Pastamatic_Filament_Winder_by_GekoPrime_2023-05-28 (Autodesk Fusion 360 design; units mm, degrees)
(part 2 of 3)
move "Move3" RotateAngle 90
move "Move4" TranslateX 0 TranslateY 0 TranslateZ -3.5 (= "-bearing_z / 2")
sketch "Sketch13" plane through (0, 0, -44.8284) normal (0, 0, -1) x axis (-1, 0, 0)
  circle C1 centre (0, 0) radius 13
  circle C2 centre (0, 0) radius 13
  circle C3 centre (0, 0) radius 10.1716
  circle C4 centre (0, 0) radius 10.1716
sketch "Sketch14" plane through (0, 0, -56.4284) normal (0, 0, 1) x axis (1, 0, 0)
  line L1 (-9.2583, 1.6082) -> (-8.3641, 1.4537)
  curve K1 (-11.9856, 0.5875) -> (-9.2583, 1.6082)
  curve K2 (-9.2583, -1.6082) -> (-11.9856, -0.5875)
  line L2 (-8.3641, -1.4537) -> (-9.2583, -1.6082)
  line L3 (-8.4354, -4.1409) -> (-7.6212, -3.7403)
  curve K3 (-10.0419, -6.5697) -> (-8.4354, -4.1409)
  curve K4 (-6.5449, -6.7429) -> (-9.3513, -7.5202)
  line L4 (-5.9123, -6.0924) -> (-6.5449, -6.7429)
  line L5 (-4.3904, -8.3082) -> (-3.9672, -7.5055)
  curve K5 (-4.2625, -11.2175) -> (-4.3904, -8.3082)
  curve K6 (-1.3315, -9.3021) -> (-3.145, -11.5805)
  line L6 (-1.2021, -8.404) -> (-1.3315, -9.3021)
  line L7 (1.3315, -9.3021) -> (1.2021, -8.404)
  curve K7 (3.145, -11.5805) -> (1.3315, -9.3021)
  curve K8 (4.3904, -8.3082) -> (4.2625, -11.2175)
  line L8 (3.9672, -7.5055) -> (4.3904, -8.3082)
  line L9 (6.5449, -6.7429) -> (5.9123, -6.0924)
  curve K9 (9.3513, -7.5202) -> (6.5449, -6.7429)
  curve K10 (8.4354, -4.1409) -> (10.0419, -6.5697)
  line L10 (7.6212, -3.7403) -> (8.4354, -4.1409)
  line L11 (9.2583, -1.6082) -> (8.3641, -1.4537)
  curve K11 (11.9856, -0.5875) -> (9.2583, -1.6082)
  curve K12 (9.2583, 1.6082) -> (11.9856, 0.5875)
  line L12 (8.3641, 1.4537) -> (9.2583, 1.6082)
  line L13 (8.4354, 4.1409) -> (7.6212, 3.7403)
  curve K13 (10.0419, 6.5697) -> (8.4354, 4.1409)
  curve K14 (6.5449, 6.7429) -> (9.3513, 7.5202)
  line L14 (5.9123, 6.0924) -> (6.5449, 6.7429)
  line L15 (4.3904, 8.3082) -> (3.9672, 7.5055)
  curve K15 (4.2625, 11.2175) -> (4.3904, 8.3082)
  curve K16 (1.3315, 9.3021) -> (3.145, 11.5805)
  line L16 (1.2021, 8.404) -> (1.3315, 9.3021)
  line L17 (-1.3315, 9.3021) -> (-1.2021, 8.404)
  curve K17 (-3.145, 11.5805) -> (-1.3315, 9.3021)
  curve K18 (-4.3904, 8.3082) -> (-4.2625, 11.2175)
  line L18 (-3.9672, 7.5055) -> (-4.3904, 8.3082)
  line L19 (-6.5449, 6.7429) -> (-5.9123, 6.0924)
  curve K19 (-9.3513, 7.5202) -> (-6.5449, 6.7429)
  curve K20 (-8.4354, 4.1409) -> (-10.0419, 6.5697)
  line L20 (-7.6212, 3.7403) -> (-8.4354, 4.1409)
  arc A1 centre (-8.1939, 2.4391) radius 1 between (-8.3641, 1.4537) and (-7.2354, 2.1538)
  arc A2 centre (0, 0) radius 12 clockwise from (-11.9856, -0.5875) to (-11.9856, 0.5875)
  arc A3 centre (-8.1939, -2.4391) radius 1 between (-7.2354, -2.1538) and (-8.3641, -1.4537)
  arc A4 centre (0, 0) radius 7.5492 clockwise from (-7.1196, -2.5104) to (-7.2354, -2.1538)
  arc A5 centre (-8.0626, -2.843) radius 1 between (-7.6212, -3.7403) and (-7.1196, -2.5104)
  arc A6 centre (0, 0) radius 12 clockwise from (-9.3513, -7.5202) to (-10.0419, -6.5697)
  arc A7 centre (-5.1953, -6.7895) radius 1 between (-4.5876, -5.9953) and (-5.9123, -6.0924)
  arc A8 centre (0, 0) radius 7.5492 clockwise from (-4.2842, -6.2158) to (-4.5876, -5.9953)
  arc A9 centre (-4.8518, -7.0391) radius 1 between (-3.9672, -7.5055) and (-4.2842, -6.2158)
  arc A10 centre (0, 0) radius 12 clockwise from (-3.145, -11.5805) to (-4.2625, -11.2175)
  arc A11 centre (-0.2123, -8.5466) radius 1 between (-0.1875, -7.5469) and (-1.2021, -8.404)
  arc A12 centre (0, 0) radius 7.5492 clockwise from (0.1875, -7.5469) to (-0.1875, -7.5469)
  arc A13 centre (0.2123, -8.5466) radius 1 between (1.2021, -8.404) and (0.1875, -7.5469)
  arc A14 centre (0, 0) radius 12 clockwise from (4.2625, -11.2175) to (3.145, -11.5805)
  arc A15 centre (4.8518, -7.0391) radius 1 between (4.2842, -6.2158) and (3.9672, -7.5055)
  arc A16 centre (0, 0) radius 7.5492 clockwise from (4.5876, -5.9953) to (4.2842, -6.2158)
  arc A17 centre (5.1953, -6.7895) radius 1 between (5.9123, -6.0924) and (4.5876, -5.9953)
  arc A18 centre (0, 0) radius 12 clockwise from (10.0419, -6.5697) to (9.3513, -7.5202)
  arc A19 centre (8.0626, -2.843) radius 1 between (7.1196, -2.5104) and (7.6212, -3.7403)
  arc A20 centre (0, 0) radius 7.5492 clockwise from (7.2354, -2.1538) to (7.1196, -2.5104)
  arc A21 centre (8.1939, -2.4391) radius 1 between (8.3641, -1.4537) and (7.2354, -2.1538)
  arc A22 centre (0, 0) radius 12 clockwise from (11.9856, 0.5875) to (11.9856, -0.5875)
  arc A23 centre (8.1939, 2.4391) radius 1 between (7.2354, 2.1538) and (8.3641, 1.4537)
  arc A24 centre (0, 0) radius 7.5492 clockwise from (7.1196, 2.5104) to (7.2354, 2.1538)
  arc A25 centre (8.0626, 2.843) radius 1 between (7.6212, 3.7403) and (7.1196, 2.5104)
  arc A26 centre (0, 0) radius 12 clockwise from (9.3513, 7.5202) to (10.0419, 6.5697)
  arc A27 centre (5.1953, 6.7895) radius 1 between (4.5876, 5.9953) and (5.9123, 6.0924)
  arc A28 centre (0, 0) radius 7.5492 clockwise from (4.2842, 6.2158) to (4.5876, 5.9953)
  arc A29 centre (4.8518, 7.0391) radius 1 between (3.9672, 7.5055) and (4.2842, 6.2158)
  arc A30 centre (0, 0) radius 12 clockwise from (3.145, 11.5805) to (4.2625, 11.2175)
  arc A31 centre (0.2123, 8.5466) radius 1 between (0.1875, 7.5469) and (1.2021, 8.404)
  arc A32 centre (0, 0) radius 7.5492 clockwise from (-0.1875, 7.5469) to (0.1875, 7.5469)
  arc A33 centre (-0.2123, 8.5466) radius 1 between (-1.2021, 8.404) and (-0.1875, 7.5469)
  arc A34 centre (0, 0) radius 12 clockwise from (-4.2625, 11.2175) to (-3.145, 11.5805)
  arc A35 centre (-4.8518, 7.0391) radius 1 between (-4.2842, 6.2158) and (-3.9672, 7.5055)
  arc A36 centre (0, 0) radius 7.5492 clockwise from (-4.5876, 5.9953) to (-4.2842, 6.2158)
  arc A37 centre (-5.1953, 6.7895) radius 1 between (-5.9123, 6.0924) and (-4.5876, 5.9953)
  arc A38 centre (0, 0) radius 12 clockwise from (-10.0419, 6.5697) to (-9.3513, 7.5202)
  arc A39 centre (-8.0626, 2.843) radius 1 between (-7.1196, 2.5104) and (-7.6212, 3.7403)
  arc A40 centre (0, 0) radius 7.5492 clockwise from (-7.2354, 2.1538) to (-7.1196, 2.5104)
loft "Loft7" sketch "Sketch13" + "Sketch14"
sketch "Sketch15" plane through (0, 0, -75.0284) normal (0, 0, 1) x axis (1, 0, 0)
  circle C1 centre (0, 0) radius 13
  circle C2 centre (0, 0) radius 13
sketch "Sketch16" plane through (0, 0, -63.4284) normal (0, 0, -1) x axis (-1, 0, 0)
  line L1 (8.4354, 4.1409) -> (7.6212, 3.7403)
  curve K1 (10.0419, 6.5697) -> (8.4354, 4.1409)
  curve K2 (6.5449, 6.7429) -> (9.3513, 7.5202)
  line L2 (5.9123, 6.0924) -> (6.5449, 6.7429)
  line L3 (4.3904, 8.3082) -> (3.9672, 7.5055)
  curve K3 (4.2625, 11.2175) -> (4.3904, 8.3082)
  curve K4 (1.3315, 9.3021) -> (3.145, 11.5805)
  line L4 (1.2021, 8.404) -> (1.3315, 9.3021)
  line L5 (-1.3315, 9.3021) -> (-1.2021, 8.404)
  curve K5 (-3.145, 11.5805) -> (-1.3315, 9.3021)
  curve K6 (-4.3904, 8.3082) -> (-4.2625, 11.2175)
  line L6 (-3.9672, 7.5055) -> (-4.3904, 8.3082)
  line L7 (-6.5449, 6.7429) -> (-5.9123, 6.0924)
  curve K7 (-9.3513, 7.5202) -> (-6.5449, 6.7429)
  curve K8 (-8.4354, 4.1409) -> (-10.0419, 6.5697)
  line L8 (-7.6212, 3.7403) -> (-8.4354, 4.1409)
  line L9 (-9.2583, 1.6082) -> (-8.3641, 1.4537)
  curve K9 (-11.9856, 0.5875) -> (-9.2583, 1.6082)
  curve K10 (-9.2583, -1.6082) -> (-11.9856, -0.5875)
  line L10 (-8.3641, -1.4537) -> (-9.2583, -1.6082)
  line L11 (-8.4354, -4.1409) -> (-7.6212, -3.7403)
  curve K11 (-10.0419, -6.5697) -> (-8.4354, -4.1409)
  curve K12 (-6.5449, -6.7429) -> (-9.3513, -7.5202)
  line L12 (-5.9123, -6.0924) -> (-6.5449, -6.7429)
  line L13 (-4.3904, -8.3082) -> (-3.9672, -7.5055)
  curve K13 (-4.2625, -11.2175) -> (-4.3904, -8.3082)
  curve K14 (-1.3315, -9.3021) -> (-3.145, -11.5805)
  line L14 (-1.2021, -8.404) -> (-1.3315, -9.3021)
  line L15 (1.3315, -9.3021) -> (1.2021, -8.404)
  curve K15 (3.145, -11.5805) -> (1.3315, -9.3021)
  curve K16 (4.3904, -8.3082) -> (4.2625, -11.2175)
  line L16 (3.9672, -7.5055) -> (4.3904, -8.3082)
  line L17 (6.5449, -6.7429) -> (5.9123, -6.0924)
  curve K17 (9.3513, -7.5202) -> (6.5449, -6.7429)
  curve K18 (8.4354, -4.1409) -> (10.0419, -6.5697)
  line L18 (7.6212, -3.7403) -> (8.4354, -4.1409)
  line L19 (9.2583, -1.6082) -> (8.3641, -1.4537)
  curve K19 (11.9856, -0.5875) -> (9.2583, -1.6082)
  curve K20 (9.2583, 1.6082) -> (11.9856, 0.5875)
  line L20 (8.3641, 1.4537) -> (9.2583, 1.6082)
  line L21 (8.4354, 4.1409) -> (7.6212, 3.7403)
  curve K21 (10.0419, 6.5697) -> (8.4354, 4.1409)
  curve K22 (6.5449, 6.7429) -> (9.3513, 7.5202)
  line L22 (5.9123, 6.0924) -> (6.5449, 6.7429)
  line L23 (4.3904, 8.3082) -> (3.9672, 7.5055)
  curve K23 (4.2625, 11.2175) -> (4.3904, 8.3082)
  curve K24 (1.3315, 9.3021) -> (3.145, 11.5805)
  line L24 (1.2021, 8.404) -> (1.3315, 9.3021)
  line L25 (-1.3315, 9.3021) -> (-1.2021, 8.404)
  curve K25 (-3.145, 11.5805) -> (-1.3315, 9.3021)
  curve K26 (-4.3904, 8.3082) -> (-4.2625, 11.2175)
  line L26 (-3.9672, 7.5055) -> (-4.3904, 8.3082)
  line L27 (-6.5449, 6.7429) -> (-5.9123, 6.0924)
  curve K27 (-9.3513, 7.5202) -> (-6.5449, 6.7429)
  curve K28 (-8.4354, 4.1409) -> (-10.0419, 6.5697)
  line L28 (-7.6212, 3.7403) -> (-8.4354, 4.1409)
  line L29 (-9.2583, 1.6082) -> (-8.3641, 1.4537)
  curve K29 (-11.9856, 0.5875) -> (-9.2583, 1.6082)
  curve K30 (-9.2583, -1.6082) -> (-11.9856, -0.5875)
  line L30 (-8.3641, -1.4537) -> (-9.2583, -1.6082)
  line L31 (-8.4354, -4.1409) -> (-7.6212, -3.7403)
  curve K31 (-10.0419, -6.5697) -> (-8.4354, -4.1409)
  curve K32 (-6.5449, -6.7429) -> (-9.3513, -7.5202)
  line L32 (-5.9123, -6.0924) -> (-6.5449, -6.7429)
  line L33 (-4.3904, -8.3082) -> (-3.9672, -7.5055)
  curve K33 (-4.2625, -11.2175) -> (-4.3904, -8.3082)
  curve K34 (-1.3315, -9.3021) -> (-3.145, -11.5805)
  line L34 (-1.2021, -8.404) -> (-1.3315, -9.3021)
  line L35 (1.3315, -9.3021) -> (1.2021, -8.404)
  curve K35 (3.145, -11.5805) -> (1.3315, -9.3021)
  curve K36 (4.3904, -8.3082) -> (4.2625, -11.2175)
  line L36 (3.9672, -7.5055) -> (4.3904, -8.3082)
  line L37 (6.5449, -6.7429) -> (5.9123, -6.0924)
  curve K37 (9.3513, -7.5202) -> (6.5449, -6.7429)
  curve K38 (8.4354, -4.1409) -> (10.0419, -6.5697)
  line L38 (7.6212, -3.7403) -> (8.4354, -4.1409)
  line L39 (9.2583, -1.6082) -> (8.3641, -1.4537)
  curve K39 (11.9856, -0.5875) -> (9.2583, -1.6082)
  curve K40 (9.2583, 1.6082) -> (11.9856, 0.5875)
  line L40 (8.3641, 1.4537) -> (9.2583, 1.6082)
  arc A1 centre (8.1939, 2.4391) radius 1 between (7.2354, 2.1538) and (8.3641, 1.4537)
  arc A2 centre (0, 0) radius 7.5492 clockwise from (7.1196, 2.5104) to (7.2354, 2.1538)
  arc A3 centre (8.0626, 2.843) radius 1 between (7.6212, 3.7403) and (7.1196, 2.5104)
  arc A4 centre (0, 0) radius 12 clockwise from (9.3513, 7.5202) to (10.0419, 6.5697)
  arc A5 centre (5.1953, 6.7895) radius 1 between (4.5876, 5.9953) and (5.9123, 6.0924)
  arc A6 centre (0, 0) radius 7.5492 clockwise from (4.2842, 6.2158) to (4.5876, 5.9953)
  arc A7 centre (4.8518, 7.0391) radius 1 between (3.9672, 7.5055) and (4.2842, 6.2158)
  arc A8 centre (0, 0) radius 12 clockwise from (3.145, 11.5805) to (4.2625, 11.2175)
  arc A9 centre (0.2123, 8.5466) radius 1 between (0.1875, 7.5469) and (1.2021, 8.404)
  arc A10 centre (0, 0) radius 7.5492 clockwise from (-0.1875, 7.5469) to (0.1875, 7.5469)
  arc A11 centre (-0.2123, 8.5466) radius 1 between (-1.2021, 8.404) and (-0.1875, 7.5469)
  arc A12 centre (0, 0) radius 12 clockwise from (-4.2625, 11.2175) to (-3.145, 11.5805)
  arc A13 centre (-4.8518, 7.0391) radius 1 between (-4.2842, 6.2158) and (-3.9672, 7.5055)
  arc A14 centre (0, 0) radius 7.5492 clockwise from (-4.5876, 5.9953) to (-4.2842, 6.2158)
  arc A15 centre (-5.1953, 6.7895) radius 1 between (-5.9123, 6.0924) and (-4.5876, 5.9953)
  arc A16 centre (0, 0) radius 12 clockwise from (-10.0419, 6.5697) to (-9.3513, 7.5202)
  arc A17 centre (-8.0626, 2.843) radius 1 between (-7.1196, 2.5104) and (-7.6212, 3.7403)
  arc A18 centre (0, 0) radius 7.5492 clockwise from (-7.2354, 2.1538) to (-7.1196, 2.5104)
  arc A19 centre (-8.1939, 2.4391) radius 1 between (-8.3641, 1.4537) and (-7.2354, 2.1538)
  arc A20 centre (0, 0) radius 12 clockwise from (-11.9856, -0.5875) to (-11.9856, 0.5875)
  arc A21 centre (-8.1939, -2.4391) radius 1 between (-7.2354, -2.1538) and (-8.3641, -1.4537)
  arc A22 centre (0, 0) radius 7.5492 clockwise from (-7.1196, -2.5104) to (-7.2354, -2.1538)
  arc A23 centre (-8.0626, -2.843) radius 1 between (-7.6212, -3.7403) and (-7.1196, -2.5104)
  arc A24 centre (0, 0) radius 12 clockwise from (-9.3513, -7.5202) to (-10.0419, -6.5697)
  arc A25 centre (-5.1953, -6.7895) radius 1 between (-4.5876, -5.9953) and (-5.9123, -6.0924)
  arc A26 centre (0, 0) radius 7.5492 clockwise from (-4.2842, -6.2158) to (-4.5876, -5.9953)
  arc A27 centre (-4.8518, -7.0391) radius 1 between (-3.9672, -7.5055) and (-4.2842, -6.2158)
  arc A28 centre (0, 0) radius 12 clockwise from (-3.145, -11.5805) to (-4.2625, -11.2175)
  arc A29 centre (-0.2123, -8.5466) radius 1 between (-0.1875, -7.5469) and (-1.2021, -8.404)
  arc A30 centre (0, 0) radius 7.5492 clockwise from (0.1875, -7.5469) to (-0.1875, -7.5469)
  arc A31 centre (0.2123, -8.5466) radius 1 between (1.2021, -8.404) and (0.1875, -7.5469)
  arc A32 centre (0, 0) radius 12 clockwise from (4.2625, -11.2175) to (3.145, -11.5805)
  arc A33 centre (4.8518, -7.0391) radius 1 between (4.2842, -6.2158) and (3.9672, -7.5055)
  arc A34 centre (0, 0) radius 7.5492 clockwise from (4.5876, -5.9953) to (4.2842, -6.2158)
  arc A35 centre (5.1953, -6.7895) radius 1 between (5.9123, -6.0924) and (4.5876, -5.9953)
  arc A36 centre (0, 0) radius 12 clockwise from (10.0419, -6.5697) to (9.3513, -7.5202)
  arc A37 centre (8.0626, -2.843) radius 1 between (7.1196, -2.5104) and (7.6212, -3.7403)
  arc A38 centre (0, 0) radius 7.5492 clockwise from (7.2354, -2.1538) to (7.1196, -2.5104)
  arc A39 centre (8.1939, -2.4391) radius 1 between (8.3641, -1.4537) and (7.2354, -2.1538)
  arc A40 centre (0, 0) radius 12 clockwise from (11.9856, 0.5875) to (11.9856, -0.5875)
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loft "Loft10" sketch "Sketch15" + "Sketch16"
combine "Combine24" bodies "spur_gear_10t_7mm"
sketch "drive" plane through (0, 0, 0) normal (0, 0, 1) x axis (-1, 0, 0)
  line L1 (-1.963, -3.4) -> (1.963, -3.4)
  line L2 (0, 0) -> (1.963, -3.4)
  line L3 (-1.963, -3.4) -> (0, 0)
  line L4 (-1.963, -5.4) -> (1.963, -5.4)
  line L5 (2.963, -5.1321) -> (1.963, -3.4)
  line L6 (-2.963, -5.1321) -> (-1.963, -3.4)
  circle C1 centre (0, 0) radius 15
  circle C2 centre (0, 0) radius 3.4
  arc A1 centre (1.963, -3.4) radius 2 clockwise from (2.963, -5.1321) to (1.963, -5.4)
  arc A2 centre (-1.963, -3.4) radius 2 clockwise from (-1.963, -5.4) to (-2.963, -5.1321)
  arc A3 centre (0, -3.4) radius 0.4156 clockwise from (0.4156, -3.4) to (-0.3636, -3.1986)
  arc A4 centre (0, -3.4) radius 2.4156 clockwise from (1.3547, -5.4) to (-1.3547, -5.4)
  point P1 (0, 0)
  point P3 (0, 0)
  point P6 (0, 0)
  point P4 (1.963, -3.4)
  point P7 (1.963, -3.4)
  point P5 (-1.963, -3.4)
  point P10 (-1.963, -3.4)
  point P13 (1.963, -3.4)
  point P16 (0.4156, -3.4)
  point P14 (0, -3.4)
  point P19 (1.3547, -5.4)
  point P17 (0, -3.4)
  point P18 (-1.3547, -5.4)
  coincident P1 P3
  tangent C2 L1
  coincident P3 P6
  equal L2 L3
  coincident P4 P7
  coincident P5 P10
  coincident P7 P13
  collinear L2 L5
  collinear L3 L6
  tangent A2 L4
  tangent A1 L4
  parallel L1 L4
  coincident L1 P16
  midpoint L1 P14
  coincident L4 P19
  coincident P14 P17
  coincident L4 P18
  horizontal L1
  dimension "d888" diameter C2 = 6.8 (= "drive_span + clearance_loose / 2")
  dimension "d889" angle L2 L3 = 60 (= "( 360 / drive_n_sides ) * 1 deg")
  dimension "d890" distance L1 L4 = 2 (= "wall_thickness")
  dimension "d892" distance A3 A4 = 2 (= "wall_thickness")
  dimension "d893" radius A3 = 0.4156 (= "drive_span / 16")
extrude "Extrude18" sketch "drive" profile of L1 L2 L3 no distance stored
circular_pattern "C-Pattern7" TotalAngle 360
loft "Loft14"
extrude "Extrude19" add of existing geometry blind 2 (= "wall_thickness") taper -45
sketch "Sketch1" plane through (0, 0, 0) normal (0, 0, 1) x axis (1, 0, 0)
  line L1 (0, 0) -> (0, 16.5831)
  line L2 (0, 125) -> (0, -125)
  line L3 (25, 16.5831) -> (-25, 16.5831)
  line L4 (0, 0) -> (-25, 16.5831)
  line L5 (25, 16.5831) -> (0, 0)
  line L6 (62.3842, 108.049) -> (175.0785, 108.049)
  line L7 (183.0785, 128.049) -> (-95, 128.049)
  line L8 (112.9635, 75.7732) -> (62.3842, 108.049)
  line L9 (112.9635, 75.7732) -> (175.0785, 108.049)
  line L10 (-18.3848, 118.5932) -> (13.1117, 87.0967)
  line L11 (183.0785, 128.049) -> (183.0785, 108.049)
  line L12 (1.8396, 51.0572) -> (30.6569, 22.24)
  line L13 (0.277, 151.3971) -> (-7.0711, 144.049)
  line L14 (183.0785, 144.049) -> (-95, 144.049)
  line L15 (183.0785, 128.049) -> (183.0785, 144.049)
  line L16 (0, 144.049) -> (0, 125)
  line L17 (-24.4187, 144.049) -> (-24.4187, 128.049)
  line L18 (-7.0711, 129.9069) -> (-7.0711, 144.049)
  line L19 (-206.2464, 96.6381) -> (-220.8848, 96.6381)
  line L20 (-220.1543, 105.5872) -> (-211.2052, 96.6381)
  line L21 (112.9635, 75.7732) -> (94.777, 86.2732)
  line L22 (131.15, 86.2732) -> (112.9635, 75.7732)
  line L23 (94.777, 86.2732) -> (131.15, 86.2732)
  line L24 (175, 65.7732) -> (67, 65.7732)
  line L25 (128.2235, 66.3204) -> (179.5938, 101.4452)
  line L26 (57.0973, 102.045) -> (97.4011, 66.5555)
  line L27 (151.8964, 82.5069) -> (143.5323, 94.7396)
  line L28 (74.8858, 86.3813) -> (83.5193, 96.1861)
  line L29 (128.2235, 66.3204) -> (119.6113, 76.6889)
  line L30 (97.4011, 66.5555) -> (106.0346, 76.3603)
  line L31 (4.1421, 126.978) -> (7.0711, 129.9069)
  line L32 (-4.1421, 126.978) -> (4.1421, 126.978)
  line L33 (-7.0711, 129.9069) -> (-4.1421, 126.978)
  line L34 (7.0711, 129.9069) -> (7.0711, 144.049)
  line L35 (-7.0711, 129.9069) -> (7.0711, 129.9069)
  line L36 (40, -14) -> (-52.1436, -14)
  line L37 (-21.6788, -11.5706) -> (-32.3575, 13.4419)
  line L38 (32.3575, 13.4419) -> (21.6788, -11.5706)
  line L39 (-14, 0) -> (-14, -10)
  line L40 (14, -10) -> (14, 0)
  line L41 (167.0785, 128.049) -> (167.0785, 108.049)
  line L42 (-180.3192, 97.2293) -> (-165.6808, 97.2293)
  line L43 (18.7877, 34.1091) -> (6.8934, 22.2148)
  line L44 (-24.002, 39.3233) -> (-6.8934, 22.2148)
  line L45 (24.4187, 144.049) -> (24.4187, 128.049)
  line L46 (-24.4187, 124.978) -> (-24.4187, 128.049)
  line L47 (24.4187, 124.978) -> (-24.4187, 124.978)
  line L48 (24.4187, 128.049) -> (24.4187, 124.978)
  circle C1 centre (0, 0) radius 125
  circle C2 centre (-25, 16.5831) radius 20
  circle C3 centre (25, 16.5831) radius 20
  circle C4 centre (62.3842, 108.049) radius 10
  circle C5 centre (112.9635, 75.7732) radius 50
  circle C6 centre (0, 0) radius 10
  circle C7 centre (112.9635, 75.7732) radius 10
  circle C8 centre (175.0785, 108.049) radius 20
  circle C9 centre (19.6153, 82.1488) radius 20
  circle C10 centre (-7.04, 52.3244) radius 20
  arc A1 centre (118.7313, -33.2588) radius 152.1279 clockwise from (-25, 16.5831) to (175.0785, 108.049)
  circle C11 centre (25, 16.5831) radius 8
  circle C12 centre (-25, 16.5831) radius 8
  circle C13 centre (-7.04, 52.3244) radius 8
  circle C14 centre (19.6153, 82.1488) radius 8
  circle C15 centre (175.0785, 108.049) radius 8
  arc A2 centre (118.7313, -33.2588) radius 144.1279 clockwise from (-17.4416, 13.9621) to (172.1153, 100.618)
  arc A3 centre (118.7313, -33.2588) radius 160.1279 clockwise from (-32.5585, 19.2039) to (178.0416, 115.48)
  arc A4 centre (0, 136.978) radius 10 clockwise from (7.0711, 144.049) to (-7.0711, 144.049)
  arc A5 centre (175.0785, 108.049) radius 8 clockwise from (178.0416, 115.48) to (172.1153, 100.618)
  arc A6 centre (-25, 16.5831) radius 8 clockwise from (-17.4416, 13.9621) to (-32.5585, 19.2039)
  circle C16 centre (-25, 16.5831) radius 24
  circle C17 centre (-7.04, 52.3244) radius 24
  circle C18 centre (19.6153, 82.1488) radius 24
  circle C19 centre (62.3842, 108.049) radius 14
  circle C20 centre (175.0785, 108.049) radius 24
  circle C21 centre (25, 16.5831) radius 24
  circle C22 centre (-25, 16.5831) radius 4.15
  circle C23 centre (25, 16.5831) radius 4.15
  circle C24 centre (-7.04, 52.3244) radius 4.15
  circle C25 centre (19.6153, 82.1488) radius 4.15
  circle C26 centre (62.3842, 108.049) radius 4.15
  circle C27 centre (175.0785, 108.049) radius 4.15
  circle C28 centre (-213.5656, 93.4087) radius 4
  circle C29 centre (-213.5656, 93.4087) radius 8
  circle C30 centre (131.15, 86.2732) radius 4.15
  circle C31 centre (94.777, 86.2732) radius 4.15
  circle C32 centre (131.15, 86.2732) radius 11
  circle C33 centre (94.777, 86.2732) radius 11
  arc A7 centre (112.9635, 75.7732) radius 12 clockwise from (102.2684, 70.3312) to (123.6586, 70.3312)
  arc A8 centre (126.4535, 68.9091) radius 3.1359 clockwise from (128.2235, 66.3204) to (123.6586, 70.3312)
  arc A9 centre (99.4735, 68.9091) radius 3.1359 clockwise from (102.2684, 70.3312) to (97.4011, 66.5555)
  circle C34 centre (131.15, 86.2732) radius 15
  circle C35 centre (94.777, 86.2732) radius 15
  circle C36 centre (0, 0) radius 100
  circle C37 centre (112.9635, 75.7732) radius 54
  circle C38 centre (0, 16.5831) radius 1
  circle C39 centre (0, 0) radius 14
  circle C40 centre (62.3842, 108.049) radius 30
  circle C41 centre (62.3842, 108.049) radius 34
  arc A10 centre (-18, -10) radius 4 clockwise from (-14, -10) to (-21.6788, -11.5706)
  arc A11 centre (18, -10) radius 4 clockwise from (21.6788, -11.5706) to (14, -10)
  arc A12 centre (0, 136.978) radius 26 clockwise from (24.4187, 128.049) to (-24.4187, 128.049)
  circle C42 centre (62.3842, 108.049) radius 8
  circle C43 centre (-173, 94) radius 4
  circle C44 centre (-173, 94) radius 8
  circle C45 centre (17.5, 11.6082) radius 4.15
  circle C46 centre (17.5, 11.6082) radius 11
  circle C47 centre (17.5, 11.6082) radius 15
  circle C48 centre (-17.5, 11.6082) radius 4.15
  circle C49 centre (-17.5, 11.6082) radius 11
  circle C50 centre (-17.5, 11.6082) radius 15
  circle C51 centre (62.3842, 108.049) radius 36
  point P1 (0, 0)
  point P2 (0, 0)
  point P9 (0, 0)
  point P10 (0, -125)
  point P11 (0, 125)
  point P7 (0, 0)
  point P15 (-7.04, 52.3244)
  point P4 (25, 16.5831)
  point P20 (25, 16.5831)
  point P8 (0, 16.5831)
  point P18 (-25, 16.5831)
  point P19 (-25, 16.5831)
  point P3 (-25, 16.5831)
  point P21 (-25, 16.5831)
  point P14 (19.6153, 82.1488)
  point P22 (-25, 16.5831)
  point P23 (0, 0)
  point P24 (0, 0)
  point P25 (25, 16.5831)
  point P13 (175.0785, 108.049)
  point P26 (175.0785, 108.049)
  point P5 (62.3842, 108.049)
  point P27 (62.3842, 108.049)
  point P30 (62.3842, 108.049)
  point P6 (112.9635, 75.7732)
  point P31 (112.9635, 75.7732)
  point P32 (175.0785, 108.049)
  point P12 (112.9635, 75.7732)
  point P33 (112.9635, 75.7732)
  point P34 (25, 16.5831)
  point P38 (175.0785, 108.049)
  point P41 (-17.4416, 13.9621)
  point P17 (175.0785, 108.049)
  point P40 (172.1153, 100.618)
  point P42 (-32.5585, 19.2039)
  point P45 (-32.5585, 19.2039)
  point P39 (118.7313, -33.2588)
  point P43 (118.7313, -33.2588)
  point P16 (118.7313, -33.2588)
  point P47 (-24.4187, 128.049)
  point P48 (183.0785, 108.049)
  point P49 (183.0785, 128.049)
  point P53 (175.0785, 108.049)
  point P56 (-32.5585, 19.2039)
  point P35 (-25, 16.5831)
  point P55 (-25, 16.5831)
  point P69 (30.6569, 22.24)
  point P70 (1.8396, 51.0572)
  point P44 (178.0416, 115.48)
  point P54 (178.0416, 115.48)
  point P72 (-32.3575, 13.4419)
  point P73 (32.3575, 13.4419)
  point P29 (183.0785, 128.049)
  point P52 (7.0711, 144.049)
  point P76 (-7.0711, 144.049)
  point P51 (-7.0711, 144.049)
  point P77 (0, 144.049)
  point P50 (0, 136.978)
  point P78 (-24.4187, 144.049)
  point P79 (0, 25.5242)
  point P80 (-7.0711, 129.9069)
  point P83 (-220.8848, 96.6381)
  point P86 (-206.2464, 96.6381)
  point P84 (-211.2052, 96.6381)
  point P88 (94.777, 86.2732)
  point P91 (94.777, 86.2732)
  point P92 (112.9635, 75.7732)
  point P93 (112.9635, 75.7732)
  point P89 (131.15, 86.2732)
  point P94 (131.15, 86.2732)
  point P96 (112.9635, 75.7732)
  point P105 (179.5938, 101.4452)
  point P109 (143.5323, 94.7396)
  point P110 (151.8964, 82.5069)
  point P111 (83.5193, 96.1861)
  point P112 (74.8858, 86.3813)
  point P113 (119.6113, 76.6889)
  point P114 (106.0346, 76.3603)
  point P115 (7.0711, 129.9069)
  point P118 (0, 0)
  point P95 (94.777, 86.2732)
  point P90 (94.777, 86.2732)
  point P120 (0, 16.5831)
  point P132 (-14, 0)
  point P133 (14, 0)
  point P134 (167.0785, 108.049)
  point P135 (167.0785, 128.049)
  point P137 (-24.4187, 128.049)
  point P136 (0, 136.978)
  point P138 (24.4187, 128.049)
  point P46 (13.1117, 87.0967)
  point P139 (-18.3848, 118.5932)
  point P106 (57.0973, 102.045)
  point P67 (62.3842, 108.049)
  point P123 (62.3842, 108.049)
  point P60 (62.3842, 108.049)
  point P122 (62.3842, 108.049)
  point P143 (-165.6808, 97.2293)
  point P144 (-180.3192, 97.2293)
  point P147 (17.5, 11.6082)
  point P148 (-17.5, 11.6082)
  point P152 (6.8934, 22.2148)
  point P153 (18.7877, 34.1091)
  point P154 (-6.8934, 22.2148)
  point P155 (-24.002, 39.3233)
  point P156 (24.4187, 144.049)
  point P157 (0, 100)
  point P119 (112.9635, 75.7732)
  coincident P1 P2
  concentric C1 C6
  tangent C2 C6
  coincident P1 P9
  vertical L1
  coincident C1 P10
  coincident C1 P11
  vertical L2
  midpoint P7 L2
  concentric C5 C7
  tangent C9 C10
  tangent C2 C10
  tangent C3 C6
  coincident P15 A1
  coincident P4 P20
  midpoint P8 L3
  coincident P18 P19
  horizontal L3
  tangent C5 C8
  coincident P3 P21
  coincident P14 A1
  coincident P3 P19
  coincident P21 P22
  coincident P1 P23
  coincident P2 P24
  coincident P4 P25
  coincident P13 P26
  coincident P5 P27
  coincident P5 A1
  horizontal L6
  horizontal L7
  equal C2 C10
  equal C2 C9
  equal C2 C8
  coincident P5 P30
  coincident P6 P31
  coincident P13 P32
  coincident P12 P33
  coincident P20 P34
  concentric C2 C12
  concentric C10 C13
  concentric C9 C14
  coincident P26 P38
  equal C11 C12
  equal C12 C13
  equal C12 C15
  tangent C12 A2
  coincident C12 P41
  coincident P17 P38
  coincident C15 P40
  coincident P42 P45
  coincident P39 P43
  coincident C12 P42
  coincident P16 P43
  tangent C12 A3
  coincident L7 P47
  coincident C15 P48
  coincident L7 P49
  perpendicular L7 L11
  tangent C15 L11
  coincident P13 P53
  coincident P42 P56
  coincident P35 P55
  concentric A6 C16
  concentric C13 C17
  concentric C14 C18
  concentric C15 C20
  equal C16 C17
  equal C16 C18
  equal C16 C20
  concentric C3 C21
  equal C16 C21
  concentric C16 C22
  concentric C3 C23
  concentric C13 C24
  concentric C14 C25
  concentric C4 C26
  concentric A5 C27
  equal C22 C23
  equal C22 C24
  equal C22 C25
  equal C22 C27
  coincident C11 P69
  coincident A2 P70
  tangent C11 L12
  tangent A4 L13
  coincident P44 P54
  tangent A2 A5
  coincident C12 P72
  coincident C11 P73
  perpendicular L11 L14
  perpendicular L14 L15
  coincident P29 P49
  coincident P52 L14
  coincident L14 P76
  coincident P51 P76
  coincident L14 P77
  perpendicular L14 L16
  coincident P50 L16
  coincident L14 P78
  perpendicular L14 L17
  coincident L2 P79
  coincident A4 P80
  concentric C28 C29
  horizontal L19
  coincident C29 P83
  coincident C29 P86
  coincident P84 L19
  coincident C28 P84
  concentric C30 C32
  equal C22 C31
  equal C22 C30
  equal C32 C33
  tangent C7 C32
  tangent C7 C33
  coincident P88 P91
  coincident P6 P92
  coincident P12 P93
  coincident P89 P94
  horizontal L23
  coincident P6 P96
  tangent A7 A8
  horizontal L24
  tangent C7 L24
  tangent A8 L24
  tangent A9 L24
  tangent A7 A9
  coincident A5 P105
  tangent A8 L25
  tangent A9 L26
  tangent C15 L25
  concentric C30 C34
  concentric C33 C35
  equal C34 C35
  coincident C34 P109
  coincident L25 P110
  perpendicular L25 L27
  coincident C35 P111
  coincident L26 P112
  perpendicular L26 L28
  tangent C35 L28
  tangent C34 L27
  equal A8 A9
  coincident C34 P113
  tangent C34 L29
  coincident C35 P114
  tangent C35 L30
  coincident A4 P115
  horizontal L32
  equal L31 L33
  perpendicular L14 L18
  perpendicular L14 L34
  tangent A4 L32
  tangent A4 L31
  coincident P1 P118
  parallel L28 L30
  concentric C7 C37
  coincident P88 P95
  coincident P88 P90
  coincident P8 P120
  tangent C21 C38
  concentric C1 C39
  concentric C4 C40
  tangent C4 C5
  tangent C9 C40
  horizontal L36
  coincident C39 P132
  coincident C39 P133
  tangent A10 L39
  tangent C39 L39
  tangent C39 L40
  tangent A11 L40
  tangent A11 L36
  tangent A10 L36
  tangent C11 L38
  tangent C12 L37
  tangent A10 L37
  tangent A11 L38
  perpendicular L36 L39
  perpendicular L36 L40
  tangent C39 L36
  tangent C17 C21
  coincident C15 P134
  coincident L7 P135
  perpendicular L7 L41
  tangent C15 L41
  coincident L7 P137
  coincident P50 P136
  coincident L7 P138
  coincident A3 P46
  tangent L10 A12
  coincident A12 P139
  coincident P47 P137
  concentric C4 C42
  equal C15 C42
  coincident P106 C42
  tangent L26 C42
  coincident P67 P123
  coincident P60 P122
  equal C13 C14
  concentric C43 C44
  coincident C44 P143
  coincident C44 P144
  horizontal L42
  equal C28 C43
  equal C29 C44
  equal L19 L42
  concentric C45 C46
  concentric C46 C47
  equal C34 C47
  equal C32 C46
  equal C30 C45
  tangent C6 C46
  coincident L5 P147
  coincident L4 P148
  concentric C48 C49
  concentric C48 C50
  equal C45 C48
  equal C46 C49
  equal C47 C50
  tangent C6 C49
  concentric C4 C51
  tangent L14 C51
  equal A10 A11
  coincident C47 P152
  coincident L12 P153
  perpendicular L12 L43
  coincident C50 P154
  coincident A3 P155
  tangent C47 L43
  tangent C50 L44
  perpendicular L43 L44
  coincident L14 P156
  perpendicular L14 L45
  coincident C36 P157
  coincident L2 P157
  perpendicular L7 L46
  perpendicular L47 L48
  perpendicular L46 L47
  dimension "d899_1" diameter C1 = 250 (= "spool_od_max")
  dimension "d900_1" diameter C6 = 20 (= "spur_gear_diameter_small")
  dimension "d1336" diameter C5 = 100 (= "spur_gear_diameter_large")
  dimension "d1345" diameter C2 = 40 (= "spur_gear_diameter_medium")
  dimension "d1347" angle L8 L9 = 120
  dimension "d1348" diameter C12 = 16 (= "bearing_id * 2")
  dimension "d1352" radius A4 = 10 (= "crossbar_od / 2")
  dimension "d1357" diameter C22 = 8.3 (= "bearing_id + clearance_loose")
  dimension "d1358" angle L2 L12 = 45
  dimension "d1361" angle L7 L13 = 45
  dimension "d1379" distance L7 L14 = 16 (= "bearing_id * 2")
  dimension "d1394" diameter C28 = 8 (= "bearing_id")
  dimension "d1395" distance C28 C29 = 4 (= "2 * wall_thickness")
  dimension "d1396" angle L19 L20 = 45
  dimension "d1434" diameter C7 = 20 (= "leadscrew_od")
  dimension "d1445" diameter C32 = 22 (= "bearing_od")
  dimension "d1446" angle L21 L22 = 120
  dimension "d1447" distance C7 A7 = 2 (= "wall_thickness")
  dimension "d1448" distance C32 C34 = 4 (= "spur_gear_clearance")
  dimension "d1449" diameter C36 = 200 (= "spool_od_bambu")
  dimension "d1451" angle L4 L5 = 112.885
  dimension "d1452" distance C5 C37 = 4 (= "spur_gear_clearance")
  dimension "d1453" distance C2 C16 = 4 (= "spur_gear_clearance")
  dimension "d1454" diameter C38 = 2 (= "wall_thickness")
  dimension "d1473" distance C6 C39 = 4 (= "spur_gear_clearance")
  dimension "d1519" distance A4 A12 = 16 (= "bearing_id * 2")
  dimension "d1520" angle L7 L10 = 45
  dimension "d1549" distance L14 P119 = 68.2759
  dimension "d1592" diameter C26 = 8.3 (= "bearing_id + clearance_loose")
  dimension "d1593" diameter C4 = 20 (= "spur_gear_diameter_small")
  dimension "d1594" distance C4 C19 = 4 (= "spur_gear_clearance")
  dimension "d1635" distance C40 C41 = 4 (= "spur_gear_clearance")
  dimension "d1636" diameter C40 = 60
  dimension "d1637" distance C41 C51 = 2 (= "wall_thickness")
  dimension "d1638" radius A10 = 4 (= "bearing_id / 2")
  dimension "d1792" distance L32 L47 = 2 (= "wall_thickness")
position "Position6"
extrude "Extrude26" cut of existing geometry no distance stored
fillet "Fillet3" radius 2 (= "wall_thickness")
sketch "Sketch38" plane through (0, 0, -60.828) normal (0, 0, 1) x axis (-1, 0, 0)
  line L1 (18.0564, 41.8174) -> (0, 0)
  line L2 (45.3505, -4.2503) -> (0, 0)
  line L3 (39.1876, 23.2177) -> (0, 0)
  line L4 (6.3211, 9.594) -> (19.8751, 40.9843)
  line L5 (45.4933, -2.255) -> (11.451, 0.9356)
  curve K1 (-48.1376, -4.0404) -> (-49.3996, -4.5314)
  curve K2 (-48.1376, -4.0404) -> (-47.4527, -3.027)
  curve K3 (-47.458, -2.9442) -> (-48.2644, -2.0247)
  curve K4 (-49.578, -1.6957) -> (-48.2644, -2.0247)
  curve K5 (-48.2644, 2.0247) -> (-49.578, 1.6957)
  curve K6 (-48.2644, 2.0247) -> (-47.458, 2.9442)
  curve K7 (-47.4527, 3.027) -> (-48.1376, 4.0404)
  curve K8 (-49.3996, 4.5314) -> (-48.1376, 4.0404)
  curve K9 (-47.6301, 8.0579) -> (-48.9745, 7.8961)
  curve K10 (-47.6301, 8.0579) -> (-46.7147, 8.8691)
  curve K11 (-46.6992, 8.9506) -> (-47.2516, 10.0418)
  curve K12 (-48.4421, 10.6871) -> (-47.2516, 10.0418)
  curve K13 (-46.2446, 13.9639) -> (-47.5987, 13.972)
  curve K14 (-46.2446, 13.9639) -> (-45.2348, 14.654)
  curve K15 (-45.2091, 14.733) -> (-45.6205, 15.8848)
  curve K16 (-46.7207, 16.6742) -> (-45.6205, 15.8848)
  curve K17 (-44.1298, 19.6498) -> (-45.4722, 19.8275)
  curve K18 (-44.1298, 19.6498) -> (-43.0415, 20.2079)
  curve K19 (-43.0061, 20.283) -> (-43.2698, 21.4773)
  curve K20 (-44.2624, 22.3984) -> (-43.2698, 21.4773)
  curve K21 (-41.319, 25.0258) -> (-42.6286, 25.3703)
  curve K22 (-41.319, 25.0258) -> (-40.1693, 25.4431)
  curve K23 (-40.1249, 25.5132) -> (-40.2368, 26.7311)
  curve K24 (-41.1061, 27.7693) -> (-40.2368, 26.7311)
  curve K25 (-37.8567, 30.0071) -> (-39.1127, 30.5131)
  curve K26 (-37.8567, 30.0071) -> (-36.6637, 30.277)
  curve K27 (-36.6108, 30.341) -> (-36.5692, 31.5633)
  curve K28 (-37.3016, 32.7023) -> (-36.5692, 31.5633)
  curve K29 (-33.7973, 34.5152) -> (-34.98, 35.1746)
  curve K30 (-33.7973, 34.5152) -> (-32.5799, 34.6335)
  curve K31 (-32.5194, 34.6903) -> (-32.3249, 35.8978)
  curve K32 (-32.9088, 37.1196) -> (-32.3249, 35.8978)
  curve K33 (-29.2049, 38.479) -> (-30.2956, 39.2814)
  curve K34 (-29.2049, 38.479) -> (-27.9823, 38.4437)
  curve K35 (-27.9151, 38.4925) -> (-27.5709, 39.6661)
  curve K36 (-27.9969, 40.9515) -> (-27.5709, 39.6661)
  curve K37 (-24.1519, 41.8359) -> (-25.1335, 42.7687)
  curve K38 (-24.1519, 41.8359) -> (-22.9433, 41.6477)
  curve K39 (-22.8706, 41.6877) -> (-22.382, 42.8089)
  curve K40 (-22.6436, 44.1375) -> (-22.382, 42.8089)
  curve K41 (-18.718, 44.533) -> (-19.575, 45.5815)
  curve K42 (-18.718, 44.533) -> (-17.5426, 44.1948)
  curve K43 (-17.4654, 44.2254) -> (-16.8401, 45.2765)
  curve K44 (-16.9332, 46.6275) -> (-16.8401, 45.2765)
  curve K45 (-12.9889, 46.5279) -> (-13.7077, 47.6755)
  curve K46 (-12.9889, 46.5279) -> (-11.8652, 46.045)
  curve K47 (-11.7848, 46.0657) -> (-11.0327, 47.0301)
  curve K48 (-10.9557, 48.3821) -> (-11.0327, 47.0301)
  curve K49 (-7.055, 47.7889) -> (-7.6243, 49.0176)
  curve K50 (-7.055, 47.7889) -> (-6.0007, 47.169)
  curve K51 (-5.9183, 47.1794) -> (-5.0512, 48.0421)
  curve K52 (-4.8054, 49.3737) -> (-5.0512, 48.0421)
  curve K53 (-1.0099, 48.2963) -> (-1.4207, 49.5866)
  curve K54 (-1.0099, 48.2963) -> (-0.0415, 47.5492)
  curve K55 (0.0415, 47.5492) -> (1.0099, 48.2963)
  curve K56 (1.4207, 49.5866) -> (1.0099, 48.2963)
  curve K57 (5.0512, 48.0421) -> (4.8054, 49.3737)
  curve K58 (5.0512, 48.0421) -> (5.9183, 47.1794)
  curve K59 (6.0007, 47.169) -> (7.055, 47.7889)
  curve K60 (7.6243, 49.0176) -> (7.055, 47.7889)
  curve K61 (11.0327, 47.0301) -> (10.9557, 48.3821)
  curve K62 (11.0327, 47.0301) -> (11.7848, 46.0657)
  curve K63 (11.8652, 46.045) -> (12.9889, 46.5279)
  curve K64 (13.7077, 47.6755) -> (12.9889, 46.5279)
  curve K65 (16.8401, 45.2765) -> (16.9332, 46.6275)
  curve K66 (16.8401, 45.2765) -> (17.4654, 44.2254)
  curve K67 (17.5426, 44.1948) -> (18.718, 44.533)
  curve K68 (19.575, 45.5815) -> (18.718, 44.533)
  curve K69 (22.382, 42.8089) -> (22.6436, 44.1375)
  curve K70 (22.382, 42.8089) -> (22.8706, 41.6877)
  curve K71 (22.9433, 41.6477) -> (24.1519, 41.8359)
  curve K72 (25.1335, 42.7687) -> (24.1519, 41.8359)
  curve K73 (27.5709, 39.6661) -> (27.9969, 40.9515)
  curve K74 (27.5709, 39.6661) -> (27.9151, 38.4925)
  curve K75 (27.9823, 38.4437) -> (29.2049, 38.479)
  curve K76 (30.2956, 39.2814) -> (29.2049, 38.479)
  curve K77 (32.3249, 35.8978) -> (32.9088, 37.1196)
  curve K78 (32.3249, 35.8978) -> (32.5194, 34.6903)
  curve K79 (32.5799, 34.6335) -> (33.7973, 34.5152)
  curve K80 (34.98, 35.1746) -> (33.7973, 34.5152)
  curve K81 (36.5692, 31.5633) -> (37.3016, 32.7023)
  curve K82 (36.5692, 31.5633) -> (36.6108, 30.341)
  curve K83 (36.6637, 30.277) -> (37.8567, 30.0071)
  curve K84 (39.1127, 30.5131) -> (37.8567, 30.0071)
  curve K85 (40.2368, 26.7311) -> (41.1061, 27.7693)
  curve K86 (40.2368, 26.7311) -> (40.1249, 25.5132)
  curve K87 (40.1693, 25.4431) -> (41.319, 25.0258)
  curve K88 (42.6286, 25.3703) -> (41.319, 25.0258)
  curve K89 (43.2698, 21.4773) -> (44.2624, 22.3984)
  curve K90 (43.2698, 21.4773) -> (43.0061, 20.283)
  curve K91 (43.0415, 20.2079) -> (44.1298, 19.6498)
  curve K92 (45.4722, 19.8275) -> (44.1298, 19.6498)
  curve K93 (45.6205, 15.8848) -> (46.7207, 16.6742)
  curve K94 (45.6205, 15.8848) -> (45.2091, 14.733)
  curve K95 (45.2348, 14.654) -> (46.2446, 13.9639)
  curve K96 (47.5987, 13.972) -> (46.2446, 13.9639)
  curve K97 (47.2516, 10.0418) -> (48.4421, 10.6871)
  curve K98 (47.2516, 10.0418) -> (46.6992, 8.9506)
  curve K99 (46.7147, 8.8691) -> (47.6301, 8.0579)
  curve K100 (48.9745, 7.8961) -> (47.6301, 8.0579)
  curve K101 (48.1376, 4.0404) -> (49.3996, 4.5314)
  curve K102 (48.1376, 4.0404) -> (47.4527, 3.027)
  curve K103 (47.458, 2.9442) -> (48.2644, 2.0247)
  curve K104 (49.578, 1.6957) -> (48.2644, 2.0247)
  curve K105 (48.2644, -2.0247) -> (49.578, -1.6957)
  curve K106 (48.2644, -2.0247) -> (47.458, -2.9442)
  curve K107 (47.4527, -3.027) -> (48.1376, -4.0404)
  curve K108 (49.3996, -4.5314) -> (48.1376, -4.0404)
  curve K109 (47.6301, -8.0579) -> (48.9745, -7.8961)
  curve K110 (47.6301, -8.0579) -> (46.7147, -8.8691)
  curve K111 (46.6992, -8.9506) -> (47.2516, -10.0418)
  curve K112 (48.4421, -10.6871) -> (47.2516, -10.0418)
  curve K113 (46.2446, -13.9639) -> (47.5987, -13.972)
  curve K114 (46.2446, -13.9639) -> (45.2348, -14.654)
  curve K115 (45.2091, -14.733) -> (45.6205, -15.8848)
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  point P3 (0, 0)
  point P4 (0, 0)
  point P8 (0, 0)
  point P10 (0, 0)
  point P1 (0, 0)
  point P6 (0, 0)
  point P19 (0, 0)
  point P17 (18.0564, 41.8174)
  point P20 (18.0564, 41.8174)
  point P21 (25.7643, 15.2648)
  point P371 (1.8882, 1.1187)
  point P22 (0, 0)
  point P77 (0, 0)
  coincident P3 P4
  coincident P3 P8
  coincident P3 P10
  coincident P1 P6
  coincident P1 P10
  coincident P3 P19
  coincident P17 P20
  parallel L1 L4
  parallel L2 L5
  coincident L3 P21
  coincident L3 P371
  dimension "d1258" distance = 2 (= "wall_thickness")
  dimension "d1259" angle L1 L2 = 72 (= "( 360 / 5 ) * 1 deg")
  dimension "d1260" distance L1 L4 = 2 (= "wall_thickness")
  dimension "d1261" radius = 2 (= "fillet_radius")
  dimension "d1263" diameter = 31.2047
  dimension "d1442" distance P22 P77 = 0 (= "1.709E-08 mm")
extrude "Extrude19" cut sketch "Sketch38" no distance stored
circular_pattern "C-Pattern1" TotalAngle 360
sketch "Sketch10" plane through (0, 0, 0) normal (0, 0, 1) x axis (1, 0, 0)
  circle C1 centre (-7.04, 52.3244) radius 4.15
  circle C2 centre (-25, 16.5831) radius 4.15
  circle C3 centre (25, 16.5831) radius 4.15
  circle C4 centre (-17.5, 11.6082) radius 4.15
  circle C5 centre (17.5, 11.6082) radius 4.15
  circle C6 centre (19.6153, 82.1488) radius 4.15
  circle C7 centre (62.3842, 108.049) radius 4.15
  circle C8 centre (94.777, 86.2732) radius 4.15
  circle C9 centre (131.15, 86.2732) radius 4.15
  circle C10 centre (175.0785, 108.049) radius 4.15
  circle C11 centre (-25, 16.5831) radius 5.15
  circle C12 centre (-17.5, 11.6082) radius 5.15
  circle C13 centre (-7.04, 52.3244) radius 5.15
  circle C14 centre (25, 16.5831) radius 5.15
  circle C15 centre (17.5, 11.6082) radius 5.15
  circle C16 centre (19.6153, 82.1488) radius 5.15
  circle C17 centre (62.3842, 108.049) radius 5.15
  circle C18 centre (94.777, 86.2732) radius 5.15
  circle C19 centre (131.15, 86.2732) radius 5.15
  circle C20 centre (175.0785, 108.049) radius 5.15
  concentric C2 C11
  concentric C4 C12
  concentric C1 C13
  concentric C3 C14
  concentric C5 C15
  concentric C6 C16
  concentric C7 C17
  concentric C8 C18
  concentric C9 C19
  concentric C10 C20
  equal C19 C20
  equal C18 C20
  equal C17 C20
  equal C16 C20
  equal C13 C20
  equal C11 C20
  equal C12 C20
  equal C15 C20
  equal C14 C20
  dimension "d1673" distance C10 C20 = 1 (= "washer_radial_thichness")
extrude "Extrude35" new body sketch "Sketch1" profile of L7 C11 C12 A2 A3 L10 L11 A4 A5 A6 C16 C17 C18 C19 C20 C21 C22 C23 C24 C25 C26 C27 L12 L14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 distance 23.2 (= "2 * stack_unit") bodies "driven_target_cradle"
extrude "Extrude36" cut sketch "Sketch1" profile of L7 C11 C12 A2 A3 L10 A6 C16 C17 C18 C19 C21 C22 C23 C24 C25 C26 L12 L26 C35 L28 C37 C39 C41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 no distance stored
extrude "Extrude51" cut sketch "Sketch1" profile of L7 A2 A3 L11 A5 C19 C20 C26 C27 L15 C30 C31 A7 A8 A9 L25 L26 C34 C35 L27 L28 L29 L30 C37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 blind 7.3 (= "bearing_z + clearance_loose") from offset 2 (= "wall_thickness")
extrude "Extrude52" sketch "Sketch1" profile of A2 A3 C19 C26 L26 C37 to an object
extrude "Extrude37" cut sketch "Sketch1" profile of L7 A4 C22 C23 C24 C25 C26 C27 L14 L31 L32 L33 L35 no distance stored
extrude "Extrude62" sketch "Sketch10" profile of C1 C2 C3 C4 C5 C6 C7 C11 C12 C13 C14 C15 C16 C17 blind 0.3 (= "washer_z") taper -45 (= "washer_taper")
extrude "Extrude63" sketch "Sketch10" profile of C1 C2 C3 C4 C5 C6 C11 C12 C13 C14 C15 C16 no distance stored taper -45 (= "washer_taper")
extrude "Extrude64" sketch "Sketch10" profile of C10 C20 blind 0.3 (= "washer_z") taper -45 (= "washer_taper")
extrude "Extrude65" sketch "Sketch10" profile of C7 C10 C17 C20 no distance stored taper -45 (= "washer_taper")
extrude "Extrude53" cut sketch "Sketch1" profile of C16 C21 C39 to an object taper 45
fillet "Fillet10" radius 16 (= "2 * bearing_id")
extrude "Extrude38" new body sketch "Sketch1" profile of L7 C11 C12 A2 A3 L10 L11 A4 A5 A6 C16 C17 C18 C19 C20 C21 C22 C23 C24 C25 C26 C27 L12 L14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 distance 11.6 (= "stack_unit") from offset 200 (= "spool_od_bambu") bodies "passive_target_cradle"
extrude "Extrude39" cut sketch "Sketch1" profile of C11 C12 A2 A3 A6 C17 C22 C23 L12 C30 C31 A7 L25 L26 C34 C35 L27 L28 L29 L30 C39 C41 L37 L38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 distance 7.3 (= "bearing_z + clearance_loose") from offset 200 (= "spool_od_bambu")
extrude "Extrude40" cut sketch "Sketch1" profile of L7 C11 C12 A2 A4 A6 L14 C30 C31 L31 L32 L33 L35 C45 C48 no distance stored
extrude "Extrude66" sketch "Sketch10" profile of C2 C3 C4 C5 C8 C9 C11 C12 C14 C15 C18 C19 blind 0.3 (= "washer_z") taper -45 (= "washer_taper")
extrude "Extrude67" sketch "Sketch10" profile of C2 C3 C4 C5 C8 C9 C11 C12 C14 C15 C18 C19 no distance stored taper -45 (= "washer_taper")
fillet "Fillet11" radius 16 (= "2 * bearing_id")
extrude "Extrude41" new body sketch "Sketch1" profile of L7 C11 C12 A2 A3 L10 L11 A4 A5 A6 C16 C17 C18 C19 C20 C21 C22 C23 C24 C25 C26 C27 L12 L14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 distance 11.6 (= "stack_unit") bodies "source_cradle"
extrude "Extrude42" cut sketch "Sketch1" profile of C11 C12 A2 A3 A6 C17 C22 C23 L12 C39 L37 L38 L39 L40 C45 C47 C48 C50 L43 L44 distance 7.3 (= "bearing_z + clearance_loose")
extrude "Extrude43" cut sketch "Sketch1" profile of L7 C11 C12 A2 A4 A6 L14 L31 L32 L33 L35 C45 C48 no distance stored
extrude "Extrude68" sketch "Sketch10" profile of C2 C3 C4 C5 C11 C12 C14 C15 no distance stored taper -45 (= "washer_taper")
extrude "Extrude69" sketch "Sketch10" profile of C2 C3 C4 C5 C11 C12 C14 C15 blind 0.3 (= "washer_z") taper -45 (= "washer_taper")
fillet "Fillet18" radius 16 (= "2 * bearing_id")
extrude "Extrude44" new body sketch "Sketch1" profile of L7 A4 L14 L35 distance 200 (= "leadscrew_length") bodies "cradle_crossbar"
chamfer "Chamfer14" distance 2 (= "wall_thickness")
extrude "Extrude54" new body sketch "Sketch1" profile of C28 C29 L19 C43 C44 L42 along normal blind 2 (= "wall_thickness") bodies "pin_long", "pin_short"
extrude "Extrude55" sketch "Sketch1" profile of C28 L19 C43 L42 blind 8 (= "bearing_id")
extrude "Extrude56" sketch "Sketch1" profile of C28 C29 L19 C43 C44 L42 blind 2 (= "wall_thickness")
extrude "Extrude57" add sketch "Sketch1" profile of C28 L19 against normal blind 31.2 (magnitude of "-stack_unit * 2 - bearing_id")
extrude "Extrude58" add sketch "Sketch1" profile of C43 L42 no distance stored
fillet "Fillet20" radius 4 (= "bearing_id / 2")
fillet "Fillet19" radius 0.6667 (= "wall_thickness / 3")
sketch "Sketch8" plane through (0, 0, 0) normal (0, 1, 0) x axis (1, 0, 0)
  line L1 (161.6576, -117.4748) -> (172.3688, -117.4748)
  line L2 (161.6576, -105.8748) -> (172.3688, -105.8748)
  line L3 (161.6576, -117.4748) -> (161.6576, -105.8748)
  line L4 (161.6576, -111.6748) -> (172.3688, -111.6748)
  line L5 (172.3688, -117.4748) -> (172.3688, -113.6748)
  line L6 (172.3688, -105.8748) -> (172.3688, -109.6748)
  line L7 (172.3688, -113.6748) -> (172.3688, -109.6748)
  line L8 (172.3688, -115.4748) -> (174.0858, -115.4748)
  line L9 (174.0858, -107.8748) -> (174.0858, -115.4748)
  arc A1 centre (167.4576, -111.6748) radius 3.8 clockwise from (169.9132, -114.5748) to (169.9132, -108.7748)
  arc A2 centre (172.3688, -117.4748) radius 3.8 clockwise from (169.9132, -114.5748) to (172.3688, -113.6748)
  arc A3 centre (172.3688, -105.8748) radius 3.8 clockwise from (172.3688, -109.6748) to (169.9132, -108.7748)
  circle C1 centre (167.4576, -111.6748) radius 5.8
  arc A4 centre (167.4576, -111.6748) radius 3.5 clockwise from (169.7194, -114.3459) to (169.7194, -109.0038)
  arc A5 centre (172.3688, -105.8748) radius 4.1 clockwise from (172.3688, -109.9748) to (169.7194, -109.0038)
  arc A6 centre (172.3688, -117.4748) radius 4.1 clockwise from (169.7194, -114.3459) to (172.3688, -113.3748)
  arc A7 centre (172.3688, -115.3937) radius 1.7188 clockwise from (172.3688, -113.6748) to (174.0858, -115.4748)
  arc A8 centre (172.3688, -107.956) radius 1.7188 clockwise from (174.0858, -107.8748) to (172.3688, -109.6748)
  arc A9 centre (172.3688, -107.956) radius 2.0188 clockwise from (174.0858, -109.018) to (172.3688, -109.9748)
  arc A10 centre (172.3688, -115.3937) radius 2.0188 clockwise from (172.3688, -113.3748) to (174.0858, -114.3316)
  point P7 (169.9132, -108.7748)
  point P12 (169.9132, -108.7748)
  point P15 (161.6576, -111.6748)
  point P6 (167.4576, -111.6748)
  point P14 (172.3688, -111.6748)
  point P9 (172.3688, -117.4748)
  point P13 (172.3688, -109.6748)
  point P17 (172.3688, -109.6748)
  point P18 (167.4576, -111.6748)
  point P11 (172.3688, -105.8748)
  point P21 (172.3688, -105.8748)
  point P23 (172.3688, -117.4748)
  point P24 (172.3688, -113.3748)
  point P22 (172.3688, -109.9748)
  point P27 (172.3688, -107.956)
  point P29 (172.3688, -115.4748)
  point P30 (172.3688, -107.956)
  point P32 (172.3688, -115.3937)
  point P31 (174.0858, -109.018)
  point P33 (174.0858, -114.3316)
  point P25 (172.3688, -115.3937)
  point P2 (172.3688, -117.4748)
  point P3 (172.3688, -105.8748)
  point P10 (172.3688, -113.6748)
  perpendicular L1 L3
  tangent A1 A2
  tangent A1 A3
  coincident P7 P12
  midpoint L3 P15
  coincident P6 L4
  concentric A1 C1
  tangent L1 C1
  perpendicular L1 L5
  perpendicular L2 L6
  midpoint P14 L7
  collinear L5 L7
  collinear L6 L7
  horizontal L1
  perpendicular L3 L4
  equal A2 A3
  coincident P9 L5
  coincident P13 P17
  equal A1 A2
  tangent L3 C1
  coincident P6 P18
  coincident P11 P21
  coincident P9 P23
  coincident L7 P24
  coincident L7 P22
  tangent A4 A6
  tangent A4 A5
  tangent A2 A7
  coincident L6 P27
  equal A7 A8
  coincident L5 P29
  perpendicular L5 L8
  vertical L9
  coincident L6 P30
  coincident L5 P32
  coincident L9 P31
  coincident L9 P33
  coincident P27 P30
  coincident P25 P32
  dimension "d1653" distance P2 P3 = 11.6 (= "stack_unit")
  dimension "d1654" distance A1 C1 = 2 (= "wall_thickness")
  dimension "d1656" distance P10 P17 = 4 (= "wall_thickness * 2")
  dimension "d1657" distance A1 A4 = 0.3 (= "clearance_loose")
  dimension "d1670" distance P23 L8 = 2 (= "wall_thickness")
extrude "Extrude59" sketch "Sketch8" profile of A1 A2 A3 L7 A4 A5 A6 A7 A8 L9 A9 A10 blind 14 (= "2 * bearing_z")
align "Align3"
move "Move2" TranslateX 0 TranslateY 0 TranslateZ -5.8 (= "-stack_unit / 2")
combine "Combine1"
extrude "Extrude60" sketch "Sketch8" profile of A1 A2 A3 L7 A4 A5 A6 A7 A8 L9 A9 A10 blind 16 (= "bearing_id * 2")
align "Align4"
combine "Combine2"
extrude "Extrude61" new body sketch "Sketch8" profile of L7 A4 A5 A6 L9 A9 A10 along normal blind 16 (= "bearing_id * 2")
align "Align5"
combine "Combine3"
chamfer "Chamfer18" distance 0.6667 (= "wall_thickness / 3")
offset_faces "OffsetFaces1"
extrude "Extrude73" new body sketch "Sketch1" profile of L7 A4 L14 L17 L31 L32 L33 A12 L45 L46 L47 L48 along normal blind 11.6 (= "stack_unit") bodies "wiper_mount_left"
